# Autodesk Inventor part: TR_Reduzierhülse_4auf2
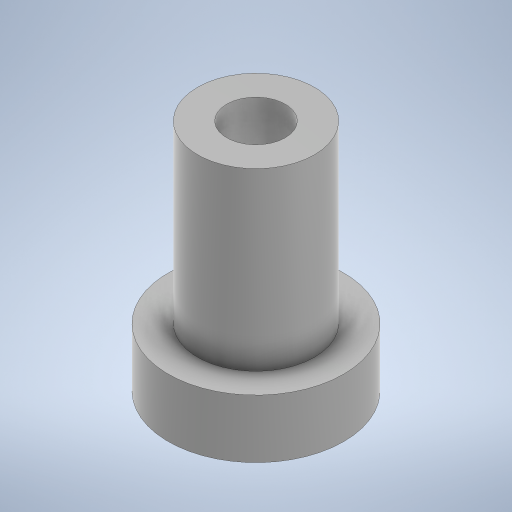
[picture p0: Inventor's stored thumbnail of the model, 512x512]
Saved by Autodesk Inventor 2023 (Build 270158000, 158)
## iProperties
Created: 2023-11
Part Number: TR_Reduzierhülse_4auf2
Material: PC/ABS-Kunststoff
Document SubType Name: Modeling
Designer: Administrator
Density: 0.357273 g/cm^3
Appearance: Glatt - Mittelgrau
Author: Administrator
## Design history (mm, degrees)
sketch "Skizze1"
  geometry: C1 r 2 at (0, 0); 1 further point
  constraints: 1 centre point, 1 coincident
  dimensions: "d0" = 4 diameter of C1
extrude "Extrusion1" new body sketch "Skizze1" distance "d1" = 6; taper "d2" = 0 deg
sketch "Skizze2"
  geometry: C1 r 3 at (0, 0); 1 further point
  constraints: 1 centre point, 1 coincident
  dimensions: "d3" = 6 diameter of C1
extrude "Extrusion2" join sketch "Skizze2" distance "d4" = 2; taper "d5" = 0 deg
sketch "Skizze3"
  geometry: C1 r 1 at (0, 0); 1 further point
  constraints: 1 centre point, 1 coincident
  dimensions: "d6" = 2 diameter of C1
extrude "Extrusion3" cut sketch "Skizze3" extent not by distance; stored distance "d7" = 0; taper "d8" = 0 deg
node "Volumenkörper1"
